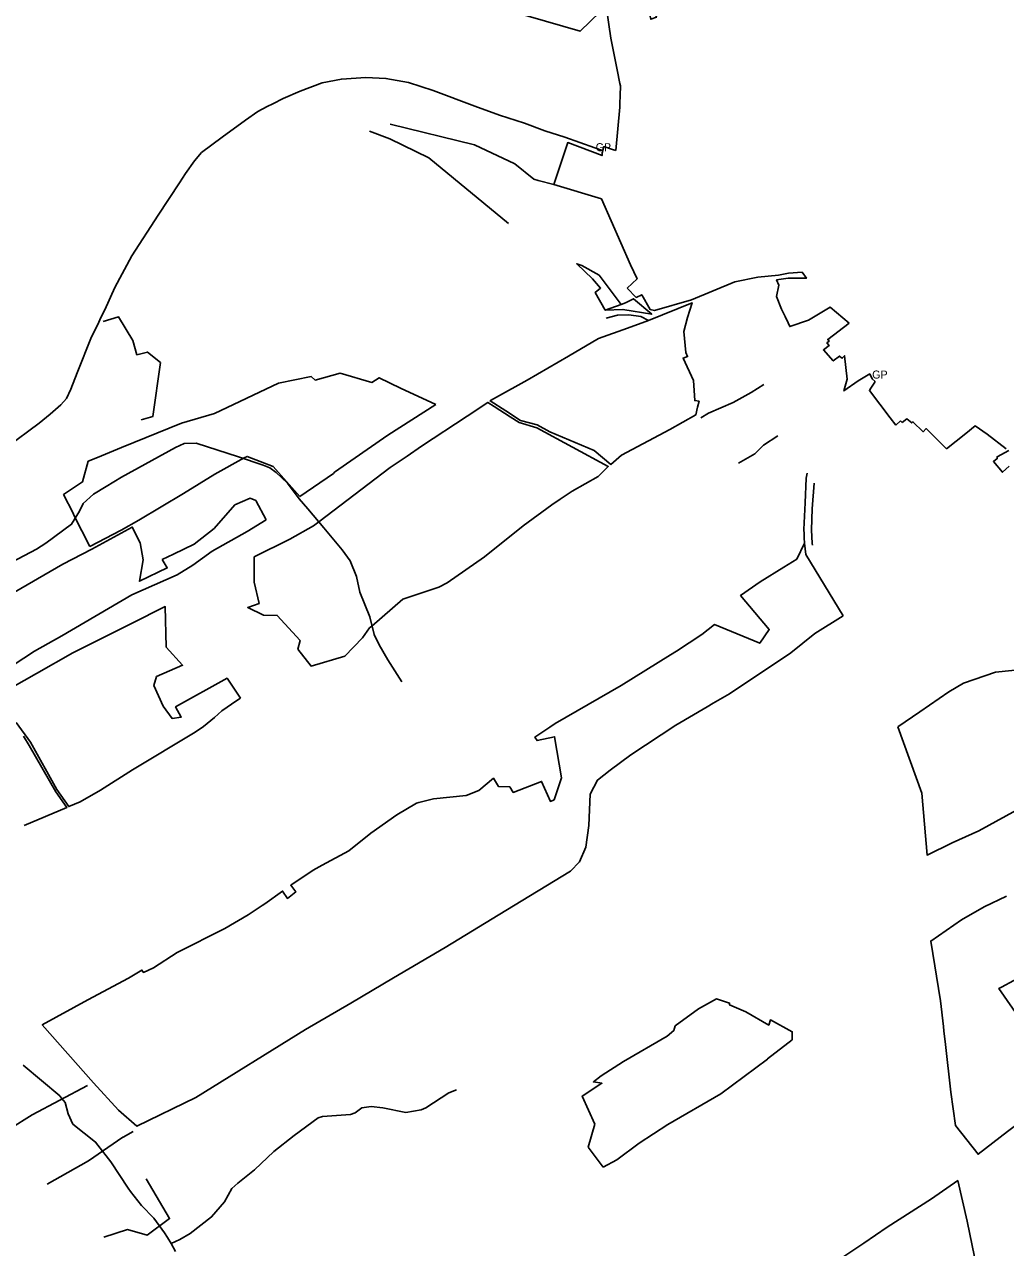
# Model space of a CAD drawing. Extents: x -617038 to -609441, y -1109294 to -1104285.
# Drawn here: x -615476 to -614251, y -1108013 to -1106486 of the extents above; entities that cross this region are included whole.
import ezdxf

# ---------------------------------------------------------------- set-up
doc = ezdxf.new("R2010")
doc.units = 0
for name, color, linetype in [('CESTY', 7, 'Continuous'), ('GRA_ZV', 7, 'Continuous'), ('LES_ZV', 7, 'Continuous'), ('OVNE_SET', 7, 'Continuous'), ('OVNI_PRE', 7, 'Continuous'), ('OVNI_SET', 7, 'Continuous'), ('VODA', 7, 'Continuous')]:
    doc.layers.add(name, color=color, linetype=linetype)

msp = doc.modelspace()

# ---------------------------------------------------------------- linework, layer by layer
at = {"layer": 'CESTY'}
msp.add_lwpolyline([(-614753.9, -1106643.3), (-614763.4, -1106640), (-614801.2, -1106626.3), (-614826.2, -1106618.6), (-614851.6, -1106609.1), (-614882.5, -1106598.8), (-614913.3, -1106587.9), (-614965.7, -1106568), (-614996.3, -1106558.4), (-615024.5, -1106553.1), (-615049.8, -1106551.8), (-615080.2, -1106554), (-615104.1, -1106558.8), (-615131.7, -1106569.2), (-615152.7, -1106578.2), (-615165.9, -1106584.9), (-615172.9, -1106588.3), (-615184.4, -1106594.5), (-615200.1, -1106605.1), (-615229, -1106626.4), (-615254.9, -1106645.6), (-615263.6, -1106656), (-615274.8, -1106672), (-615282.5, -1106683.4), (-615308.9, -1106724.1), (-615342, -1106774.7), (-615363.2, -1106814.1), (-615375.5, -1106842), (-615380.8, -1106851.9), (-615384.4, -1106860.6), (-615392.1, -1106876), (-615410.1, -1106920.8), (-615418.2, -1106941.2), (-615423.7, -1106952.9), (-615430.4, -1106960.6), (-615444, -1106972.6), (-615457.7, -1106983.6), (-615498, -1107013.6)], dxfattribs=at)
at = {"layer": 'GRA_ZV'}
for points in [[(-614749.2, -1106465.6), (-614754.1, -1106468.3), (-614757.1, -1106469.9), (-614781.8, -1106494.1), (-614914.7, -1106455.6)], [(-614893.9, -1106955.4), (-614894.4, -1106955.9), (-614874.6, -1106968.3), (-614856.4, -1106980.2), (-614835.5, -1106985.9), (-614819.7, -1106994.6), (-614764.4, -1107018), (-614743.6, -1107035.2), (-614730.2, -1107023.5), (-614670.1, -1106991.5), (-614637.5, -1106973.3), (-614635.2, -1106963.8), (-614633.4, -1106956.4), (-614638.7, -1106955.4), (-614640.2, -1106930.2), (-614653.4, -1106902.4), (-614647.7, -1106900.6), (-614650, -1106895.4), (-614652.6, -1106869.4), (-614647.9, -1106851.6), (-614641.9, -1106833.4), (-614696.4, -1106855.6), (-614722.6, -1106865.1), (-614759.1, -1106878.1), (-614796.7, -1106900), (-614848.2, -1106929.8), (-614886.6, -1106951.3), (-614893.9, -1106955.4)], [(-615394.4, -1107137.7), (-615414.2, -1107098.7), (-615415.4, -1107096.2), (-615427.2, -1107073), (-615403.5, -1107057.1), (-615396.3, -1107031.2), (-615384.6, -1107026.4), (-615354.8, -1107014.2), (-615280, -1106983.5), (-615238.5, -1106971.6), (-615158.8, -1106933.6), (-615117.9, -1106925.5), (-615112.9, -1106929.8), (-615081.9, -1106921.4), (-615042.2, -1106932.7), (-615032.9, -1106926.9), (-615006.5, -1106939.8), (-614962.1, -1106960.3)], [(-614817.3, -1107085.7), (-614807.1, -1107078.8), (-614799.5, -1107073.7), (-614791.9, -1107068.6), (-614759.5, -1107050.5), (-614746.8, -1107037.8), (-614836.1, -1106989.4), (-614858, -1106982.8), (-614869.3, -1106975.6), (-614889.4, -1106962.8), (-614897.3, -1106957.8), (-614923, -1106974.9), (-614980, -1107012.6), (-614998.1, -1107024.8), (-615019.2, -1107039.1), (-615108.4, -1107106.9), (-615111.8, -1107109.5), (-615115, -1107111.9), (-615144.7, -1107128.5), (-615189.3, -1107150.6)], [(-614962.1, -1106960.3), (-615022.3, -1106998.7), (-615088.7, -1107045), (-615090.2, -1107046.5), (-615132.1, -1107075.1)], [(-615132.1, -1107075.1), (-615165.3, -1107037.8), (-615197.9, -1107025.2), (-615201.6, -1107027.2), (-615238.1, -1107047.4), (-615277.2, -1107071.6), (-615333, -1107104.8), (-615355.3, -1107117.3), (-615394.4, -1107137.7)], [(-615174.3, -1107104.3), (-615187.2, -1107080.4), (-615194.3, -1107077.5), (-615213.2, -1107085.8), (-615239, -1107115.1)], [(-615189.3, -1107150.6), (-615189.2, -1107182.1), (-615183, -1107208.9), (-615197.1, -1107213.8), (-615177.4, -1107223.6), (-615160.3, -1107223.9), (-615131.8, -1107255.3), (-615134.6, -1107266.1), (-615118, -1107287.1), (-615076, -1107274.8), (-615053.8, -1107251.7), (-615045.1, -1107239.5), (-615042.3, -1107237.1), (-615003.4, -1107203.7), (-614958.3, -1107188.5), (-614948.1, -1107183.3), (-614901.3, -1107150.8), (-614853.3, -1107112.1), (-614817.3, -1107085.7)], [(-615516.1, -1107302.6), (-615463.7, -1107268.6), (-615429.2, -1107249.4), (-615342.1, -1107198.3), (-615285.1, -1107173.2), (-615265.9, -1107161), (-615241.5, -1107143.6), (-615197.9, -1107118.9), (-615174.3, -1107104.3)], [(-615304.2, -1107153.8), (-615297.6, -1107164.4), (-615332.5, -1107181.1), (-615327.7, -1107154.4), (-615331.7, -1107133), (-615341.4, -1107113.4), (-615392, -1107140.9), (-615428.2, -1107159.8), (-615496.4, -1107199.2), (-615531.8, -1107220.4), (-615561.5, -1107240.2), (-615593.9, -1107260.6), (-615637.9, -1107281), (-615724.5, -1107321.7), (-615763.2, -1107335.8), (-615798.3, -1107346.1), (-615819.1, -1107356.9), (-615833, -1107362)], [(-615239, -1107115.1), (-615264.1, -1107135), (-615290, -1107147.5), (-615304.2, -1107153.8)], [(-614453.5, -1107224.3), (-614500.1, -1107147.7), (-614501.6, -1107133.4), (-614511.5, -1107153.4), (-614527.7, -1107163.7), (-614557.1, -1107182), (-614581.5, -1107199.1), (-614545.7, -1107241.6), (-614557.6, -1107258.6), (-614614.3, -1107235.3), (-614629.9, -1107247.5), (-614661.7, -1107268.4), (-614669.2, -1107273.2), (-614730.9, -1107311.3), (-614813.3, -1107358.7), (-614820, -1107363.3), (-614838.5, -1107375.8), (-614835.8, -1107380.1), (-614813.8, -1107375.4), (-614805.1, -1107426.8), (-614814.4, -1107454.1), (-614819, -1107456.2), (-614830.2, -1107431.1), (-614865.6, -1107444.9), (-614869.9, -1107438), (-614884, -1107437.4), (-614890.3, -1107427.2), (-614908.3, -1107442.3), (-614924.3, -1107448.6), (-614965.1, -1107452.9), (-614983.3, -1107457.6), (-614986.3, -1107458.4), (-615010.8, -1107473.1), (-615043.6, -1107495.7), (-615071, -1107517.7), (-615104.3, -1107535.8), (-615115.5, -1107542.1)], [(-615342.5, -1107234), (-615300.1, -1107212.8), (-615299, -1107263.6), (-615278.6, -1107286), (-615311, -1107300.3), (-615314.3, -1107311.2), (-615302.8, -1107337), (-615291.7, -1107352.5), (-615280.3, -1107350.9), (-615287.3, -1107338.2), (-615222.9, -1107302.4), (-615206.3, -1107327.1)], [(-615643.9, -1107420), (-615612.6, -1107397), (-615562.7, -1107361.3), (-615555.4, -1107356.4), (-615492, -1107313.7), (-615461.1, -1107296.3), (-615415.5, -1107270.4), (-615342.5, -1107234)], [(-615115.5, -1107542.1), (-615143.4, -1107560.9), (-615137.1, -1107569.1), (-615147.5, -1107577.4), (-615153.6, -1107568.2), (-615175.7, -1107584.1), (-615179.2, -1107586.1), (-615196.7, -1107597.6), (-615225.7, -1107614.9), (-615285.3, -1107645), (-615314.9, -1107664.2), (-615327.5, -1107669.8), (-615329.4, -1107666.9), (-615346.2, -1107677.1), (-615396.9, -1107703.9), (-615453.8, -1107735.3), (-615389.6, -1107807.8), (-615358.6, -1107841.7), (-615335.6, -1107861.6), (-615262.1, -1107825.9), (-615125.1, -1107740.9), (-615068.2, -1107708.1), (-615015, -1107676.5), (-614950.6, -1107638.5), (-614874.8, -1107592.3), (-614794, -1107543.2), (-614782.9, -1107531.7), (-614774.7, -1107513.4), (-614771.3, -1107486.1), (-614769.3, -1107447.1), (-614760.3, -1107429.5), (-614752.4, -1107423.3), (-614744.4, -1107417.1), (-614718.5, -1107397.9), (-614662.3, -1107360.9), (-614623.4, -1107337.9), (-614615.8, -1107333.4), (-614595.5, -1107321.8), (-614518.7, -1107270.5), (-614488.9, -1107246.6), (-614453.5, -1107224.3)], [(-614124.8, -1107300.9), (-614095.3, -1107294.4), (-614072.7, -1107287.9), (-614075.7, -1107292.2), (-614091.9, -1107306.5), (-614103.9, -1107316.5), (-614104.1, -1107316.7), (-614114.9, -1107325.3), (-614104.4, -1107337), (-614097.5, -1107395.5), (-614121.2, -1107409.1), (-614141.8, -1107424.2), (-614169.6, -1107435.4), (-614228.7, -1107462.6), (-614284, -1107493), (-614317.4, -1107507.8), (-614348.5, -1107523.2), (-614355.3, -1107445.9), (-614385, -1107362.8)], [(-614385, -1107362.8), (-614357.8, -1107344.4), (-614321.6, -1107319.4), (-614303.3, -1107308.5), (-614263.2, -1107294.7), (-614226.4, -1107290.8), (-614162.4, -1107301.9), (-614124.8, -1107300.9)], [(-615206.3, -1107327.1), (-615210.9, -1107330.2), (-615229.7, -1107342.9), (-615238.7, -1107351.2), (-615252.2, -1107362.5), (-615263, -1107369.5), (-615340.9, -1107416.8), (-615381.2, -1107442), (-615406.4, -1107456.5), (-615420.8, -1107462.7), (-615435.6, -1107441.2), (-615468.6, -1107382.1), (-615486.2, -1107357.4)], [(-615477.3, -1107374.5), (-615470.2, -1107386.1), (-615436.9, -1107444.3), (-615423.3, -1107463.8), (-615476.3, -1107486.4)], [(-614313, -1107860.8), (-614319, -1107819.2), (-614325.7, -1107759.9), (-614327.7, -1107742.8), (-614328.3, -1107737.2), (-614331.9, -1107705.2), (-614344, -1107630.5), (-614305.7, -1107604), (-614277.2, -1107587.8), (-614249.3, -1107574.4)], [(-614313, -1107860.8), (-614284.8, -1107896.9), (-614248.1, -1107868.5), (-614241.5, -1107863.4), (-614214.8, -1107842.7), (-614171, -1107821.3), (-614181.8, -1107803.4), (-614224.9, -1107738.9), (-614258.9, -1107689.8), (-614255.5, -1107688), (-614209.6, -1107663)], [(-614753.1, -1107912.8), (-614771.9, -1107888), (-614763.7, -1107859.2), (-614779.3, -1107824.2), (-614754.8, -1107808.1), (-614765.4, -1107806.6), (-614755.8, -1107799), (-614727.7, -1107781.1), (-614673.4, -1107749.5), (-614664.9, -1107742.2), (-614663.1, -1107736.6), (-614634.3, -1107715.1), (-614611.6, -1107702.8), (-614595.2, -1107708.1), (-614595.4, -1107710.2), (-614575.1, -1107719.1), (-614546.3, -1107735.6), (-614544.2, -1107729), (-614517, -1107743.8), (-614517.3, -1107753.8), (-614547.8, -1107777.6), (-614548.1, -1107777.9), (-614606.3, -1107821.3), (-614672.5, -1107859.7), (-614708.3, -1107882.9), (-614736, -1107903.7), (-614753.1, -1107912.8)], [(-614779.4, -1108203.9), (-614743.8, -1108185.1), (-614730.7, -1108178.7), (-614679.3, -1108149.5), (-614635.6, -1108123.6), (-614553, -1108081.8), (-614486.5, -1108047), (-614427.5, -1108007.7), (-614398.3, -1107987.9), (-614343, -1107952.4), (-614310.2, -1107929.7), (-614298.7, -1107980.4), (-614280.8, -1108067.4), (-614325.3, -1108096.8), (-614367.6, -1108122.1), (-614474.7, -1108187), (-614551.4, -1108229.1), (-614613.9, -1108259.3), (-614640.7, -1108270.6), (-614669.7, -1108256.7), (-614707.6, -1108231.9), (-614716.6, -1108228), (-614736.8, -1108219.1), (-614779.4, -1108203.9)]]:
    msp.add_lwpolyline(points, dxfattribs=at)
at = {"layer": 'LES_ZV'}
for p, q in [((-614839.7, -1106678.9), (-614834.4, -1106680.7)), ((-614834.4, -1106680.7), (-614815, -1106685.7)), ((-615352.7, -1107875.5), (-615340.2, -1107868.6))]:
    msp.add_line(p, q, dxfattribs=at)
for points in [[(-614871.3, -1106734.3), (-614970.8, -1106652.1), (-615019.7, -1106628.4), (-615044.9, -1106618.8)], [(-614839.7, -1106678.9), (-614863.7, -1106659.8), (-614914.1, -1106636.1), (-615019.3, -1106610.1)], [(-614750.8, -1106842.4), (-614730.7, -1106835.3), (-614758.3, -1106799), (-614779.7, -1106786.6), (-614786.2, -1106784.5), (-614766.4, -1106803.4), (-614756.4, -1106814.9), (-614763.1, -1106820.3), (-614750.8, -1106842.4)], [(-614730.7, -1106835.3), (-614725.5, -1106833.4), (-614715.4, -1106828.3), (-614692.5, -1106847.7), (-614728.5, -1106841.7), (-614750.8, -1106842.4)], [(-615377.8, -1106856.7), (-615358.7, -1106850.8), (-615340.8, -1106880.6), (-615335.7, -1106898.5)], [(-614749.5, -1106852.4), (-614735.1, -1106848.8), (-614721, -1106848.3), (-614706.3, -1106850.4), (-614696.4, -1106855.6)], [(-615335.7, -1106898.5), (-615322.5, -1106894.9), (-615306.1, -1106908.1), (-615315.7, -1106975.5), (-615330.4, -1106979.7)], [(-614631, -1106976.9), (-614621.5, -1106971.4), (-614590.8, -1106957.7), (-614568.5, -1106945.4), (-614552.7, -1106935.5)], [(-614584.2, -1107033.6), (-614563.8, -1107021.8), (-614552.8, -1107011.2), (-614535.2, -1106999.7)], [(-614498.4, -1107046.2), (-614499.5, -1107052.5), (-614500.9, -1107083.3), (-614502.4, -1107116.7), (-614502.2, -1107121.8), (-614502, -1107126.9), (-614501.6, -1107133.4)], [(-614489.7, -1107058.7), (-614492, -1107090.5), (-614492.9, -1107116.8), (-614492, -1107133.9), (-614491.7, -1107135.9)], [(-615557.7, -1107899.3), (-615521.3, -1107875.3), (-615494.3, -1107865.3), (-615466.6, -1107847.5), (-615397.4, -1107811.1)], [(-614771.9, -1107888), (-614763.7, -1107859.2), (-614779.3, -1107824.2), (-614754.8, -1107808.1), (-614765.4, -1107806.6)], [(-615447.8, -1107934.4), (-615396.2, -1107905), (-615353.2, -1107875.6), (-615352.7, -1107875.5)], [(-615376.8, -1108000.5), (-615347.2, -1107991), (-615322.7, -1107997.8), (-615294.7, -1107977.3), (-615324.1, -1107927.5)]]:
    msp.add_lwpolyline(points, dxfattribs=at)
at = {"layer": 'OVNI_PRE'}
msp.add_line((-614559.8, -1106801.2), (-614534, -1106798.9), dxfattribs=at)
msp.add_lwpolyline([(-614324.2, -1107015.8), (-614349.7, -1106990.4), (-614353.7, -1106994.5), (-614366.2, -1106982), (-614367.7, -1106983.4), (-614373.8, -1106978.3), (-614379.8, -1106982.9)], dxfattribs=at)
at = {"layer": 'OVNI_SET'}
for p, q in [((-614588.9, -1106807.3), (-614559.8, -1106801.2)), ((-614381.7, -1106980.8), (-614387.5, -1106986.4)), ((-614379.8, -1106982.9), (-614381.7, -1106980.8)), ((-614324.2, -1107015.8), (-614300.4, -1106996.8))]:
    msp.add_line(p, q, dxfattribs=at)
for points in [[(-614699, -1106438.2), (-614686.7, -1106476.6), (-614693.8, -1106479.2), (-614702.9, -1106440.4), (-614749.2, -1106465.6), (-614743.7, -1106502.8)], [(-614743.7, -1106502.8), (-614735.7, -1106542.2), (-614732.2, -1106559.3), (-614731.6, -1106562.3), (-614732, -1106574.3), (-614732.3, -1106584.5), (-614732.5, -1106589), (-614737.3, -1106643.3)], [(-614754.5, -1106646.1), (-614754.5, -1106649.4), (-614797.4, -1106633.2), (-614815, -1106685.7), (-614755.2, -1106703.3)], [(-614754.5, -1106646.1), (-614752.2, -1106638.2), (-614741.7, -1106641.8), (-614737.3, -1106643.3)], [(-614755.2, -1106703.3), (-614719.1, -1106785.9), (-614710.9, -1106803.3), (-614723.3, -1106815.2)], [(-614723.3, -1106815.2), (-614712, -1106826.6), (-614705, -1106823.3), (-614694.6, -1106841.6), (-614688.9, -1106842.9), (-614642.8, -1106829.5), (-614588.9, -1106807.3)], [(-614534, -1106798.9), (-614521.7, -1106796.5), (-614504.7, -1106795.1), (-614499.3, -1106802.6), (-614522, -1106802.7), (-614536.5, -1106804.7), (-614533.6, -1106811.5), (-614536.7, -1106825.3), (-614530.3, -1106841.2), (-614525.7, -1106850.5), (-614522.1, -1106858.5), (-614520.1, -1106863), (-614496.8, -1106854.9), (-614469.7, -1106839), (-614446, -1106858.7)], [(-614446, -1106858.7), (-614472.6, -1106879.1), (-614470.7, -1106881.1), (-614473.7, -1106883.5), (-614471.1, -1106886.8), (-614478.1, -1106892.2), (-614465.9, -1106905.9), (-614458.1, -1106900), (-614455.2, -1106902.7)], [(-614455.2, -1106902.7), (-614454.3, -1106901.9), (-614451.6, -1106899.4), (-614448.5, -1106928.9), (-614452.5, -1106943.5), (-614434.8, -1106930.7), (-614420.3, -1106922.1), (-614417.1, -1106928.5), (-614413.5, -1106931.5)], [(-614413.5, -1106931.5), (-614414.9, -1106933.7), (-614418.8, -1106940), (-614420.6, -1106942.9), (-614394.6, -1106977.1), (-614387.5, -1106986.4)], [(-614300.4, -1106996.8), (-614288.4, -1106987.1), (-614273.4, -1106997.6), (-614249.8, -1107015.8)], [(-614246.4, -1107017.9), (-614261.1, -1107025.7), (-614260.9, -1107028), (-614265.7, -1107031.7), (-614254.5, -1107045), (-614246, -1107037.3)]]:
    msp.add_lwpolyline(points, dxfattribs=at)
at = {"layer": 'VODA'}
for points in [[(-615499.6, -1107161.6), (-615460.9, -1107141.2), (-615449.3, -1107133.7), (-615417.1, -1107110), (-615407.3, -1107093.8), (-615402.7, -1107083.9), (-615389.7, -1107072.2), (-615373.8, -1107063), (-615354.9, -1107051.1), (-615287.4, -1107014), (-615276.4, -1107008.9), (-615261.7, -1107008.6), (-615208.6, -1107025.9), (-615177.9, -1107036), (-615169.4, -1107039.4), (-615161.5, -1107045.2), (-615147.5, -1107058.8), (-615132.9, -1107078.4), (-615122.1, -1107090.6), (-615102.1, -1107114.4), (-615079.1, -1107142), (-615069.3, -1107155.7), (-615061.5, -1107175.1), (-615057, -1107194.8), (-615044.7, -1107225.4), (-615039.2, -1107247.8), (-615032.8, -1107260.6), (-615022.2, -1107279.3), (-615004.8, -1107306.9)], [(-615477.6, -1107785.7), (-615431.7, -1107824), (-615431.3, -1107824.6), (-615425, -1107832.4), (-615421.3, -1107846.5), (-615415.5, -1107859.1), (-615387.2, -1107881.7), (-615384.3, -1107885.4), (-615368, -1107906.2), (-615346.5, -1107939), (-615343.7, -1107943.2), (-615329.8, -1107960.9), (-615314.6, -1107976.8), (-615301.1, -1107994.8), (-615297.5, -1108000.8), (-615292.9, -1108008.5), (-615287.2, -1108018.2)], [(-614936.5, -1107816.3), (-614945.9, -1107820), (-614974.6, -1107838.7), (-614980.7, -1107841.3), (-614999.8, -1107844.6), (-615028.6, -1107838.9), (-615042.8, -1107837.3), (-615054.5, -1107838.9), (-615063, -1107845.2), (-615069, -1107847.3), (-615103.6, -1107849.8), (-615109.3, -1107851.5), (-615139.3, -1107873.3), (-615164.5, -1107893.5), (-615188.9, -1107916.4), (-615209.5, -1107932.9), (-615216.9, -1107939.5), (-615226.3, -1107956.4), (-615242.3, -1107975.2), (-615269.1, -1107995.8), (-615281.8, -1108003.5), (-615292.9, -1108008.5)]]:
    msp.add_lwpolyline(points, dxfattribs=at)

# ---------------------------------------------------------------- texts
at = {"layer": 'OVNE_SET'}
for p in [(-614762.6, -1106644), (-614417.2, -1106928)]:
    msp.add_text('GP', height=10, dxfattribs=at).set_placement(p)

doc.saveas('drawing.dxf')
